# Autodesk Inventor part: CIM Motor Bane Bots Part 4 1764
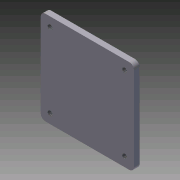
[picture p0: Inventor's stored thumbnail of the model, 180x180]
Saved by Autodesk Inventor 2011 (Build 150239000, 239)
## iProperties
Created: 2010-01
Part Number: CIM Motor Bane Bots Part 4 1764
Document SubType Name: Modeling
Designer: cmcfadden
Density: 1 g/cm^3
Author: cmcfadden
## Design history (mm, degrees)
sketch "Sketch1"
  geometry: L1 (-27.967, 19.992)-(29.183, 19.992); L2 (32.358, 16.817)-(32.358, -40.333); L3 (29.183, -43.508)-(-27.967, -43.508); L4 (-31.142, -40.333)-(-31.142, 16.817); A1 r 3.175 centre (29.183, 16.817) between (32.358, 16.817) and (29.183, 19.992); A2 r 3.175 centre (29.183, -40.333) between (29.183, -43.508) and (32.358, -40.333); A3 r 3.175 centre (-27.967, -40.333) between (-31.142, -40.333) and (-27.967, -43.508); A4 r 3.175 centre (-27.967, 16.817) between (-27.967, 19.992) and (-31.142, 16.817); 5 further points
  constraints: 8 end point, 8 point on circle, 8 point on line, 8 tangent, 4 centre point, 3 equal radius, 2 parallel, 1 horizontal, 1 perpendicular
  dimensions: "d0" = 63.5 distance of point (-31.142, 19.992) point (32.358, 19.992); "d1" = 63.5 distance of point (32.358, 19.992) point (32.358, -43.508); "d26" = 3.175 radius of A1
extrude "Extrusion1" new body sketch "Sketch1" distance "d2" = 3.81; taper "d3" = 0 deg
sketch "Sketch2"
  geometry: L1 (32.358, 16.817)-(32.358, -40.333) reference; L2 (-27.967, 19.992)-(29.183, 19.992) reference; L3 (-31.142, -40.333)-(-31.142, 16.817) reference; L4 (29.183, -43.508)-(-27.967, -43.508) reference; C1 r 1.587 at (-24.792, 13.642); C2 r 1.587 at (26.008, 13.642); C3 r 1.587 at (26.008, -37.158); C4 r 1.587 at (-24.792, -37.158); 5 further points
  constraints: 4 centre point
  dimensions: "d4" = 3.175 diameter of C1; "d5" = 3.175 diameter of C2; "d6" = 3.175 diameter of C4; "d7" = 3.175 diameter of C3; "d8" = 6.35 distance from line of L2 C1.centre; "d9" = 6.35 distance from line of L3 C1.centre; "d10" = 6.35 distance from line of L2 C2.centre; "d11" = 6.35 distance from line of L1 C2.centre; "d12" = 6.35 distance from line of L1 C3.centre; "d13" = 6.35 distance from line of L4 C3.centre; "d14" = 6.35 distance from line of L4 C4.centre; "d15" = 6.35 distance from line of L3 C4.centre
extrude "Extrusion2" cut sketch "Sketch2" stored distance "d16" = 3.81; taper "d17" = 0 deg
thread "Thread1" dims "d18" = 25.4, "d19" = 0
thread "Thread2" dims "d20" = 25.4, "d21" = 0
thread "Thread3" dims "d22" = 25.4, "d23" = 0
thread "Thread4" dims "d24" = 25.4, "d25" = 0
body "Solid1"
